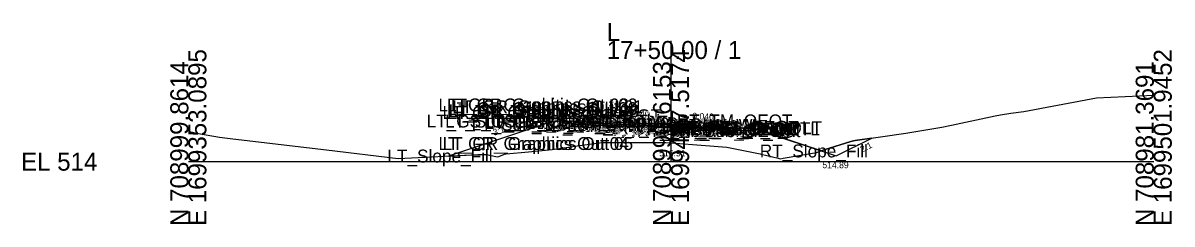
# Model space of a CAD drawing. Extents: x -63 to 1153, y -24 to 9522.
# Drawn here: x -25.7 to 152.8, y 9490.3 to 9521.5 of the extents above; entities that cross this region are included whole.
import ezdxf

# ---------------------------------------------------------------- set-up
doc = ezdxf.new("R2010")
doc.units = 0
for name, color, linetype in [('Default', 7, 'Continuous'), ('Exist Cross Section Cell', 7, 'Continuous'), ('Exist XS Center Line Elevation Label', 7, 'Continuous'), ('Exist XS Ground Line', 7, 'Continuous'), ('Prop CMT DNC', 7, 'Continuous'), ('Prop CMT Pvmt Course 1', 7, 'Continuous'), ('Prop CMT Pvmt Course 2', 7, 'Continuous'), ('Prop CMT Pvmt Surface', 7, 'Continuous'), ('Prop CMT Pvmt Surface Overlay', 7, 'Continuous'), ('Prop CMT Pvmt Surface Shoulder', 7, 'Continuous'), ('Prop CMT Shld Paved Course 1', 7, 'Continuous'), ('Prop CMT Shld Paved Course 2', 7, 'Continuous'), ('Prop CMT Slope Grass', 7, 'Continuous'), ('Prop CMT Subgrade Earthwork', 7, 'Continuous'), ('Prop XS Ditch Standard Text', 7, 'Continuous'), ('Prop XS Earthwork Shape', 7, 'Continuous'), ('Prop XS EOT Tick Mark', 7, 'Continuous'), ('Prop XS SE Text', 7, 'Continuous'), ('Prop XS Side Slope Text', 7, 'Continuous')]:
    doc.layers.add(name, color=color, linetype=linetype)

msp = doc.modelspace()

# ---------------------------------------------------------------- linework, layer by layer
at = {"layer": 'Exist Cross Section Cell'}
for p, q in [((75, 9500), (75, 9518.75)), ((0, 9500), (75, 9500)), ((75, 9500), (150, 9500))]:
    msp.add_line(p, q, dxfattribs=at)
at = {"layer": 'Exist XS Ground Line'}
msp.add_lwpolyline([(0, 9504.68), (0.39, 9504.61), (1.6, 9504.38), (4.82, 9503.78), (6.91, 9503.53), (21.45, 9501.82), (32.61, 9500.47), (44.97, 9501.1), (46.34, 9501.11), (47.79, 9500.81), (48.09, 9500.73), (49.3, 9501.2), (49.39, 9501.21), (52.85, 9501.52), (56.52, 9501.89), (58.4, 9502.17), (60.8, 9502.5), (64.32, 9502.97), (67.66, 9502.97), (74.18, 9502.97), (75, 9502.91), (80.37, 9502.51), (83.67, 9502.27), (88.86, 9501.19), (88.99, 9501.17), (91.62, 9500.55), (91.98, 9500.43), (92.42, 9500.54), (97.59, 9501.4), (98.8, 9501.83), (102.94, 9503.11), (103.34, 9503.24), (103.63, 9503.28), (111.5, 9504.44), (116.74, 9505.31), (117.07, 9505.35), (118.57, 9505.68), (125.36, 9507.1), (126.18, 9507.27), (127.77, 9507.53), (129.83, 9507.81), (141.09, 9509.93), (150, 9510.33)], dxfattribs=at)
at = {"layer": 'Prop CMT Pvmt Course 1'}
for points in [[(75, 9505.73), (65, 9506.13)], [(65, 9506.13), (65, 9505.88)], [(65, 9505.88), (75, 9505.48)], [(75, 9505.61), (75, 9505.73)], [(75, 9505.73), (85, 9505.33)], [(75, 9505.61), (75, 9505.73)], [(75, 9505.48), (75, 9505.61), (75, 9505.61)], [(75, 9505.48), (75, 9505.61), (75, 9505.61)], [(85, 9505.08), (75, 9505.48)], [(85, 9505.33), (85, 9505.08)]]:
    msp.add_lwpolyline(points, dxfattribs=at)
at = {"layer": 'Prop CMT Pvmt Course 2'}
for points in [[(75, 9505.48), (65, 9505.88)], [(65, 9505.88), (65, 9505.63)], [(65, 9505.63), (75, 9505.23)], [(75, 9505.23), (75, 9505.48)], [(75, 9505.23), (75, 9505.48)], [(75, 9505.48), (85, 9505.08)], [(85, 9504.83), (75, 9505.23)], [(85, 9505.08), (85, 9504.83)]]:
    msp.add_lwpolyline(points, dxfattribs=at)
at = {"layer": 'Prop CMT Pvmt Surface'}
for points in [[(75, 9505.73), (65, 9506.13)], [(75, 9505.73), (85, 9505.33)]]:
    msp.add_lwpolyline(points, dxfattribs=at)
at = {"layer": 'Prop CMT Pvmt Surface Overlay'}
for points in [[(75, 9505.73), (65, 9506.13)], [(75, 9505.73), (85, 9505.33)]]:
    msp.add_lwpolyline(points, dxfattribs=at)
at = {"layer": 'Prop CMT Pvmt Surface Shoulder'}
for points in [[(65, 9506.13), (60.28, 9506.32)], [(85, 9505.33), (85.01, 9505.33)]]:
    msp.add_lwpolyline(points, dxfattribs=at)
at = {"layer": 'Prop CMT Shld Paved Course 1'}
for points in [[(65, 9506.13), (60.28, 9506.32), (60.04, 9506.08)], [(60.04, 9506.08), (65, 9505.88)], [(65, 9505.88), (65, 9506.13)], [(85, 9505.33), (85.01, 9505.33), (85.27, 9505.07)], [(85, 9505.08), (85, 9505.33)], [(85.27, 9505.07), (85, 9505.08)]]:
    msp.add_lwpolyline(points, dxfattribs=at)
at = {"layer": 'Prop CMT Shld Paved Course 2'}
for points in [[(60.04, 9506.08), (59.8, 9505.84)], [(59.8, 9505.84), (65, 9505.63)], [(65, 9505.88), (60.04, 9506.08)], [(60.04, 9506.08), (60.04, 9506.08)], [(65, 9505.63), (65, 9505.88)], [(85, 9505.08), (85.27, 9505.07)], [(85, 9504.83), (85, 9505.08)], [(85.53, 9504.81), (85, 9504.83)], [(85.27, 9505.07), (85.27, 9505.07)], [(85.27, 9505.07), (85.53, 9504.81)]]:
    msp.add_lwpolyline(points, dxfattribs=at)
at = {"layer": 'Prop CMT Slope Grass'}
for p, q in [((88, 9505.1), (100.65, 9500.88)), ((100.65, 9500.88), (106.2, 9503.66))]:
    msp.add_line(p, q, dxfattribs=at)
for points in [[(56.56, 9506.25), (40.42, 9500.87)], [(59.56, 9506.31), (56.56, 9506.25)], [(60.28, 9506.32), (59.56, 9506.31)], [(85.01, 9505.33), (88, 9505.1)]]:
    msp.add_lwpolyline(points, dxfattribs=at)
at = {"layer": 'Prop CMT Subgrade Earthwork'}
for points in [[(59.8, 9505.84), (59.33, 9506.3)], [(65, 9505.63), (59.8, 9505.84)], [(75, 9505.23), (65, 9505.63)], [(75, 9505.23), (85, 9504.83)], [(85.53, 9504.81), (85.97, 9505.26)], [(85, 9504.83), (85.53, 9504.81)]]:
    msp.add_lwpolyline(points, dxfattribs=at)
at = {"layer": 'Prop XS Earthwork Shape'}
for points in [[(64.32, 9502.97), (67.66, 9502.97), (74.18, 9502.97), (75, 9502.91), (80.37, 9502.51), (83.67, 9502.27), (88.86, 9501.19), (88.99, 9501.17), (91.62, 9500.55), (91.98, 9500.43), (92.42, 9500.54), (97.59, 9501.4), (98.32, 9501.66), (88, 9505.1), (85.97, 9505.26), (85.53, 9504.81), (85, 9504.83), (75, 9505.23), (65, 9505.63), (59.8, 9505.84), (59.33, 9506.3), (56.56, 9506.25), (40.42, 9500.87), (44.97, 9501.1), (46.34, 9501.11), (47.79, 9500.81), (48.09, 9500.73), (49.3, 9501.2), (49.39, 9501.21), (52.85, 9501.52), (56.52, 9501.89), (58.4, 9502.17), (60.8, 9502.5)], [(100.65, 9500.88), (106.2, 9503.66), (103.63, 9503.28), (103.34, 9503.24), (102.94, 9503.11), (98.8, 9501.83), (98.32, 9501.66)]]:
    msp.add_lwpolyline(points, close=True, dxfattribs=at)
at = {"layer": 'Prop XS EOT Tick Mark'}
for points in [[(65, 9506.13), (65, 9507.13)], [(85, 9505.33), (85, 9506.33)]]:
    msp.add_lwpolyline(points, dxfattribs=at)

# ---------------------------------------------------------------- texts
at = {"layer": 'Default'}
msp.add_text('-', height=0.0001, dxfattribs=at).set_placement((0, 9500))
at = {"layer": 'Exist Cross Section Cell'}
for s, p in [('L', (65, 9518.75)), ('17+50.00 / 1', (65, 9515.95)), ('EL 514', (-26, 9498.6))]:
    msp.add_text(s, height=2.8, dxfattribs=at).set_placement(p)
for s, p in [('E 1699353.0895', (2.8, 9490)), ('E 1699427.5174', (77.8, 9490)), ('E 1699501.9452', (152.8, 9490)), ('N 708999.8614', (0, 9490)), ('N 708990.6153', (75, 9490)), ('N 708981.3691', (150, 9490))]:
    msp.add_text(s, height=2.8, rotation=90, dxfattribs=at).set_placement(p)
at = {"layer": 'Exist XS Center Line Elevation Label'}
msp.add_text('516.91', height=1, dxfattribs=at).set_placement((73.16, 9500.82))
at = {"layer": 'Prop CMT DNC'}
for s, p in [('LT_GR_Graphics Out 03', (38.86, 9507.81)), ('LT_GR_Graphics Out 06', (39.48, 9506.64)), ('LT_GR_Graphics Out 02', (40.19, 9507.81)), ('LT_GR_Graphics Out 09', (40.19, 9507.23)), ('LT_GR_Graphics Out 07', (40.19, 9506.64)), ('LT_GR_Graphics Out 08', (40.46, 9506.93)), ('LT_GR_Graphics Out 01', (41.03, 9507.52)), ('LT_GS_OS_GR_Face_Graphics', (37.02, 9505.31)), ('LT_Sub_Trench_Out_DLT', (39.9, 9505.3)), ('LT_Sub_Trench_Out', (44, 9504.84)), ('LT_GS_OS_CTL', (45.93, 9505.25)), ('LT_PS2_Shelf_Out', (46.02, 9505.08)), ('LT_PS2_OEOP', (50.27, 9505.08)), ('LT_PS1_OEOP', (51.08, 9505.32)), ('LT_PV2_OEOT', (55.17, 9504.88)), ('LT_PV1_OEOT', (55.74, 9505.13)), ('LT_TM_OEOT', (55.94, 9506.13)), ('RT_TM_OEOT', (75.9, 9505.33)), ('LT_Sub_OEOT', (55.08, 9504.63)), ('RT_PV1_OEEOP_W', (62.94, 9504.61)), ('LT_PV1_OEEOP_W', (62.98, 9504.61)), ('RT_Sub_OEEOP', (64.17, 9504.23)), ('LT_Sub_OEEOP', (64.21, 9504.23)), ('RT_PV2_OEEOP', (64.26, 9504.48)), ('LT_PV2_OEEOP', (64.31, 9504.48)), ('RT_Sub_Trench_Out_DLT', (66.49, 9504.26)), ('PV1_PGL_W', (67.58, 9504.61)), ('PV1_PGL', (69.47, 9504.73)), ('RT_Sub_Trench_Out', (69.69, 9503.81)), ('RT_PS2_Shelf_Out', (71.21, 9504.07)), ('RT_Sub_OEOT', (75.03, 9503.83)), ('RT_PV2_OEOT', (75.13, 9504.08)), ('RT_PS2_OEOP', (75.46, 9504.07)), ('RT_PV1_OEOT', (75.69, 9504.33)), ('RT_PS1_OEOP', (75.77, 9504.33)), ('RT_GS_OS_CTL', (77.32, 9504.1)), ('LT_GR_Graphics Out 04', (38.86, 9501.81)), ('LT_GR_Graphics Out 05', (39.52, 9501.81)), ('LT_Slope_Fill', (30.93, 9499.87)), ('RT_Slope_Fill', (88.79, 9500.66))]:
    msp.add_text(s, height=2, dxfattribs=at).set_placement(p)
at = {"layer": 'Prop XS Ditch Standard Text'}
msp.add_text('514.89', height=1, dxfattribs=at).set_placement((98.51, 9498.98))
at = {"layer": 'Prop XS SE Text'}
for p in [(68.29, 9507), (78.29, 9506.6)]:
    msp.add_text('0.040', height=1, rotation=357.7094, dxfattribs=at).set_placement(p)
at = {"layer": 'Prop XS Side Slope Text'}
for s, rotation, p in [('3:1', 18.4332, (47.5, 9504.02)), ('3:1', 341.5651, (91.06, 9504.44)), ('2:1', 26.5651, (104.69, 9501.4))]:
    msp.add_text(s, height=1, rotation=rotation, dxfattribs=at).set_placement(p)

doc.saveas('drawing.dxf')
